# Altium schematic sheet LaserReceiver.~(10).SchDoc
size A; DocumentNumber: 4; SheetNumber: 4; SheetTotal: 6
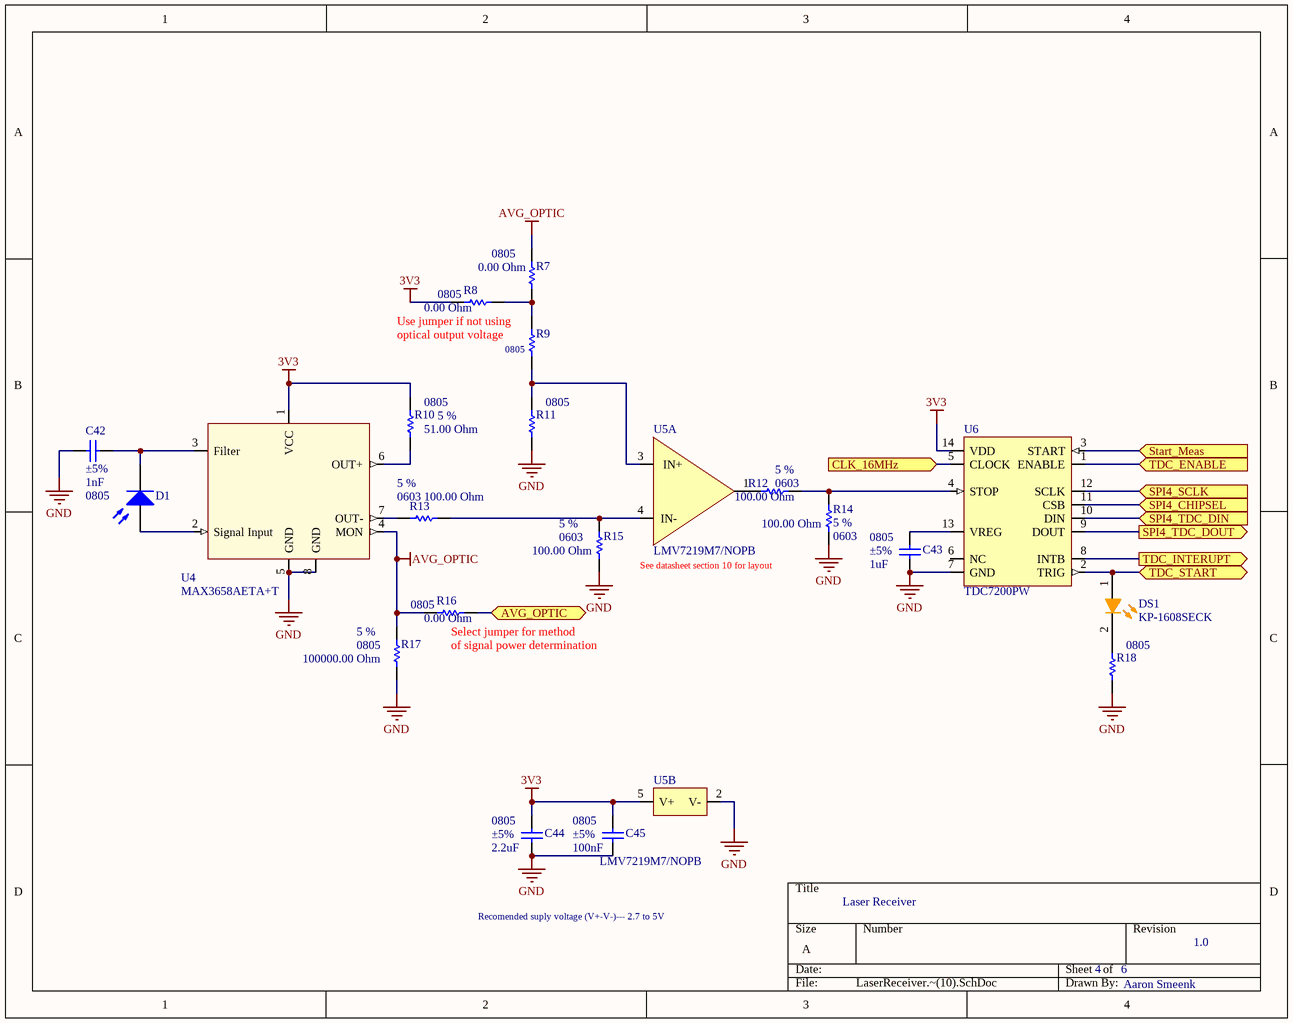
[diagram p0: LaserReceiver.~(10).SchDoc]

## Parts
C42  value 1nF  Tolerance: ±5%  Case-EIA: 0805  [CAPC0805(2012)100_M]  (hidden comment: CAP 1nF 6.3V 0805(2012))
C43  value 1uF  Tolerance: ±5%  Case-EIA: 0805  [CAPC0805(2012)100_M]  (hidden comment: CAP 1uF 6.3V 0805(2012))
C44  value 2.2uF  Tolerance: ±5%  Case-EIA: 0805  [CAPC0805(2012)100_M]  (hidden comment: CAP 2.2uF 6.3V 0805(2012))
C45  value 100nF  Tolerance: ±5%  Case-EIA: 0805  [CAPC0805(2012)100_M]  (hidden comment: CAP 100nF 6.3V 0805(2012))
D1  Photo Sen  [PIN2]  (value not drawn)
DS1  KP-1608SECK  [KING-0603LED_ORANGE_V]
R7  value 0.00 Ohm  Case-EIA: 0805  [RESC0805(2012)_N]  (hidden comment: Jumper 0805(2012))
R8  value 0.00 Ohm  Case-EIA: 0805  [RESC0805(2012)_N]  (hidden comment: Jumper 0805(2012))
R9  Case-EIA: 0805  [RESC0805(2012)_N]  (hidden comment: 51R 5% 0805(2012))
R10  value 51.00 Ohm  Tolerance: 5 %  Case-EIA: 0805  [RESC0805(2012)_N]  (hidden comment: 51R 5% 0805(2012))
R11  Case-EIA: 0805  [RESC0805(2012)_N]  (hidden comment: 51R 5% 0805(2012))
R12  value 100.00 Ohm  Tolerance: 5 %  Case-EIA: 0603  [RESC0603(1608)_L]  (hidden comment: 100R 5% 0603(1608))
R13  value 100.00 Ohm  Tolerance: 5 %  Case-EIA: 0603  [RESC0603(1608)_L]  (hidden comment: 100R 5% 0603(1608))
R14  value 100.00 Ohm  Tolerance: 5 %  Case-EIA: 0603  [RESC0603(1608)_L]  (hidden comment: 100R 5% 0603(1608))
R15  value 100.00 Ohm  Tolerance: 5 %  Case-EIA: 0603  [RESC0603(1608)_L]  (hidden comment: 100R 5% 0603(1608))
R16  value 0.00 Ohm  Case-EIA: 0805  [RESC0805(2012)_N]  (hidden comment: Jumper 0805(2012))
R17  value 100000.00 Ohm  Tolerance: 5 %  Case-EIA: 0805  [RESC0805(2012)_L]  (hidden comment: 100K 5% 0805(2012))
R18  Case-EIA: 0805  [RESC0805(2012)_N]  (hidden comment: 51R 5% 0805(2012))
U4  MAX3658AETA+T  [MAX3658AETA+T--QFN0P300X300X80_HS-9N]
U5  LMV7219M7/NOPB  (parts A,B of 2)
U6  TDC7200PW  [TDC7200PW--TSOP65P640X120-14N]

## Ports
AVG_OPTIC, CLK_16MHz (in), SPI4_CHIPSEL (in), SPI4_SCLK (in), SPI4_TDC_DIN (in), SPI4_TDC_DOUT (out), Start_Meas (in), TDC_ENABLE (in), TDC_INTERUPT (out), TDC_START

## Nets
3V3: C44.2 C45.2 R8.1 R10.2 U4.1(VCC) U5.5(V+) U6.14(VDD)
AVG_OPTIC: R7.2 R16.1 R17.2 U4.4(MON)
GND: C42.1 C43.1 C44.1 C45.1 R11.1 R14.2 R15.1 R17.1 R18.1 U4.5(GND) U4.8(GND) U4.9(PAD) U5.2(V-) U6.7(GND)
AVG_OPTIC: R16.2 ; port AVG_OPTIC  [a separate net that carries the same name]
CLK_16MHz: U6.5(CLOCK) ; port CLK_16MHz
SPI4_CHIPSEL: U6.11(CSB) ; port SPI4_CHIPSEL
SPI4_SCLK: U6.12(SCLK) ; port SPI4_SCLK
SPI4_TDC_DIN: U6.10(DIN) ; port SPI4_TDC_DIN
SPI4_TDC_DOUT: U6.9(DOUT) ; port SPI4_TDC_DOUT
Start_Meas: U6.3(START) ; port Start_Meas
TDC_ENABLE: U6.1(ENABLE) ; port TDC_ENABLE
TDC_INTERUPT: U6.8(INTB) ; port TDC_INTERUPT
TDC_START: DS1.1(A) U6.2(TRIG) ; port TDC_START
NetC42_2: C42.2 D1.2(K) U4.3(Filter)
NetC43_2: C43.2 U6.13(VREG)
NetD1_1: D1.1(A) U4.2(Signal_Input)
NetDS1_2: DS1.2(K) R18.2
NetR7_1: R7.1 R8.2 R9.2
NetR9_1: R9.1 R11.2 U5.3(IN+)
NetR10_1: R10.1 U4.6(OUT+)
NetR12_1: R12.1 R14.1 U6.4(STOP)
NetR12_2: R12.2 U5.1(OUT)
NetR13_1: R13.1 U4.7(OUT-)
NetR13_2: R13.2 R15.2 U5.4(IN-)

Not connected (* = marked no-connect by the designer): U6 6(NC)

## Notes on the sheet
- (near R9) Use jumper if not using
- (near R9) optical output voltage
- See datasheet section 10 for layout
- (near R16) Select jumper for method
- (near R16) of signal power determination
- Laser Receiver
- Recomended suply voltage (V+-V-)--- 2.7 to 5V
- 4
- 6
- 1.0
- Aaron Smeenk

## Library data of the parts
C42 = CMP-1036-02947-1: CAP 1nF 6.3V ±5% 0805 (2012 Metric) Thickness 1mm SMD; Case-Metric: 2012
C43 = CMP-1036-02947-1: CAP 1uF 6.3V ±5% 0805 (2012 Metric) Thickness 1mm SMD; Case-Metric: 2012
C44 = CMP-1036-02947-1: CAP 2.2unF 6.3V ±5% 0805 (2012 Metric) Thickness 1mm SMD; Case-Metric: 2012
C45 = CMP-1036-02947-1: CAP 100nF 6.3V ±5% 0805 (2012 Metric) Thickness 1mm SMD; Case-Metric: 2012
D1 = Photo Sen: Photosensitive Diode
DS1 = CMP-0404-00002-1: LED, SMT, 0603(1608), 1.1mm thickness, Orange; Manufacturer: Kingbright; Power Dissipation: 75 mW; Packing Type: 2000 pcs / reel; Reverse Voltage: 5 V; Forward Current: 30 mA
R7 R8 R16 = CMP-1013-00001-1: Jumper 0805 (2012 Metric); Tolerance: None; Case-Metric: 2012
R9 R11 R18 = CMP-1013-00043-1: 51R 0.125W 5% 0805 (2012 Metric)  SMD; Value: 51.00 Ohm; Case-Metric: 2012
R10 = CMP-1013-00043-1: 51R 0.125W 5% 0805 (2012 Metric)  SMD; Case-Metric: 2012
R12-R15 = CMP-1012-00050-1: 100R 0.1W 5% 0603 (1608 Metric)  SMD; Case-Metric: 1608
R17 = CMP-1013-00122-1: 100K 0.125W 5% 0805 (2012 Metric)  SMD; Case-Metric: 2012
U4 = MAX3658AETA+T: IC AMP TRANSIMPEDANCE 8-TDFN
U5 = LMV7219M7/NOPB: IC COMPARATOR SC-70-5
U6 = TDC7200PW: STATIC ULTRASONIC FLOWMETER AF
